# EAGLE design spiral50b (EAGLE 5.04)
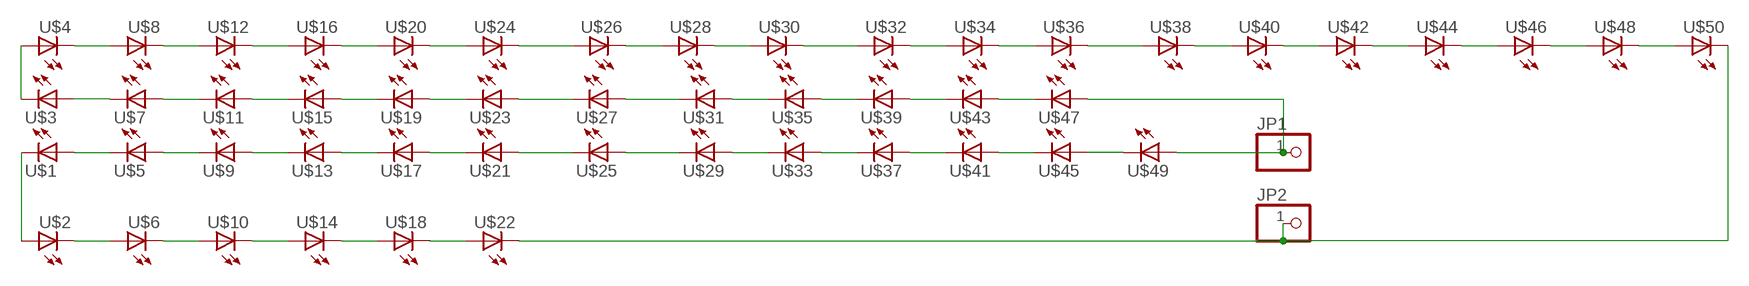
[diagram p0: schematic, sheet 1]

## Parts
JP1  PINHD-1X1  [1X01]
JP2  PINHD-1X1  [1X01]
U$1  LED5MM  [LED5MM]
U$2  LED5MM  [LED5MM]
U$3  LED5MM  [LED5MM]
U$4  LED5MM  [LED5MM]
U$5  LED5MM  [LED5MM]
U$6  LED5MM  [LED5MM]
U$7  LED5MM  [LED5MM]
U$8  LED5MM  [LED5MM]
U$9  LED5MM  [LED5MM]
U$10  LED5MM  [LED5MM]
U$11  LED5MM  [LED5MM]
U$12  LED5MM  [LED5MM]
U$13  LED5MM  [LED5MM]
U$14  LED5MM  [LED5MM]
U$15  LED5MM  [LED5MM]
U$16  LED5MM  [LED5MM]
U$17  LED5MM  [LED5MM]
U$18  LED5MM  [LED5MM]
U$19  LED5MM  [LED5MM]
U$20  LED5MM  [LED5MM]
U$21  LED5MM  [LED5MM]
U$22  LED5MM  [LED5MM]
U$23  LED5MM  [LED5MM]
U$24  LED5MM  [LED5MM]
U$25  LED5MM  [LED5MM]
U$26  LED5MM  [LED5MM]
U$27  LED5MM  [LED5MM]
U$28  LED5MM  [LED5MM]
U$29  LED5MM  [LED5MM]
U$30  LED5MM  [LED5MM]
U$31  LED5MM  [LED5MM]
U$32  LED5MM  [LED5MM]
U$33  LED5MM  [LED5MM]
U$34  LED5MM  [LED5MM]
U$35  LED5MM  [LED5MM]
U$36  LED5MM  [LED5MM]
U$37  LED5MM  [LED5MM]
U$38  LED5MM  [LED5MM]
U$39  LED5MM  [LED5MM]
U$40  LED5MM  [LED5MM]
U$41  LED5MM  [LED5MM]
U$42  LED5MM  [LED5MM]
U$43  LED5MM  [LED5MM]
U$44  LED5MM  [LED5MM]
U$45  LED5MM  [LED5MM]
U$46  LED5MM  [LED5MM]
U$47  LED5MM  [LED5MM]
U$48  LED5MM  [LED5MM]
U$49  LED5MM  [LED5MM]
U$50  LED5MM  [LED5MM]

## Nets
N$1: U$1.A U$5.K(C)
N$2: U$3.A U$7.K(C)
N$3: U$5.A U$9.K(C)
N$4: U$7.A U$11.K(C)
N$5: U$11.A U$15.K(C)
N$6: U$15.A U$19.K(C)
N$7: U$19.A U$23.K(C)
N$8: U$23.A U$27.K(C)
N$9: U$27.A U$31.K(C)
N$10: U$9.A U$13.K(C)
N$11: U$13.A U$17.K(C)
N$12: U$17.A U$21.K(C)
N$13: U$21.A U$25.K(C)
N$14: U$25.A U$29.K(C)
N$15: U$31.A U$35.K(C)
N$16: U$35.A U$39.K(C)
N$17: U$39.A U$43.K(C)
N$18: U$43.A U$47.K(C)
N$19: U$29.A U$33.K(C)
N$20: U$33.A U$37.K(C)
N$21: U$37.A U$41.K(C)
N$22: U$41.A U$45.K(C)
N$23: U$1.K(C) U$2.A
N$24: U$2.K(C) U$6.A
N$25: U$45.A U$49.K(C)
N$26: U$6.K(C) U$10.A
N$27: U$10.K(C) U$14.A
N$28: U$14.K(C) U$18.A
N$29: U$18.K(C) U$22.A
N$30: U$4.K(C) U$8.A
N$31: U$8.K(C) U$12.A
N$32: U$12.K(C) U$16.A
N$33: U$16.K(C) U$20.A
N$34: U$20.K(C) U$24.A
N$35: U$24.K(C) U$26.A
N$36: U$26.K(C) U$28.A
N$37: U$28.K(C) U$30.A
N$38: U$30.K(C) U$32.A
N$39: U$32.K(C) U$34.A
N$40: U$3.K(C) U$4.A
N$41: U$34.K(C) U$36.A
N$42: U$36.K(C) U$38.A
N$43: U$38.K(C) U$40.A
N$44: U$40.K(C) U$42.A
N$45: U$42.K(C) U$44.A
N$46: U$44.K(C) U$46.A
N$47: U$46.K(C) U$48.A
N$48: U$48.K(C) U$50.A
N$49: JP2.1 U$22.K(C) U$50.K(C)
N$51: JP1.1 U$47.A U$49.A

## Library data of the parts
JP1 JP2 = pinhead:PINHD-1X1: PIN HEADER
U$1-U$50 = led(2):LED: LED

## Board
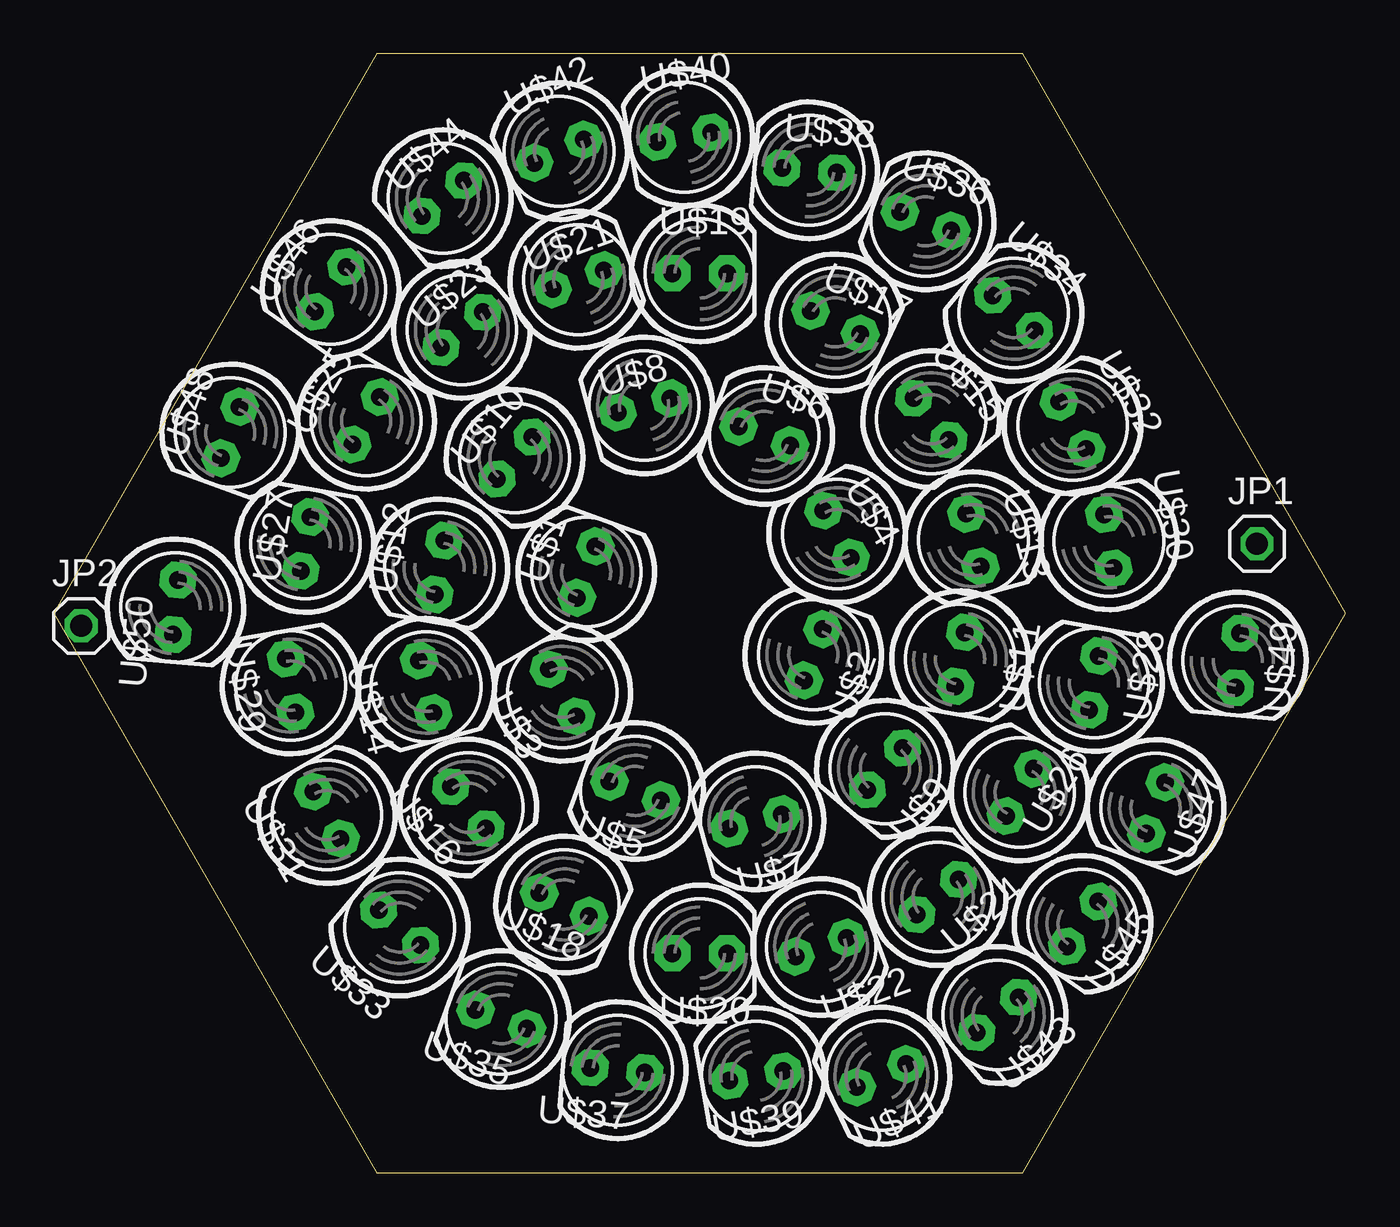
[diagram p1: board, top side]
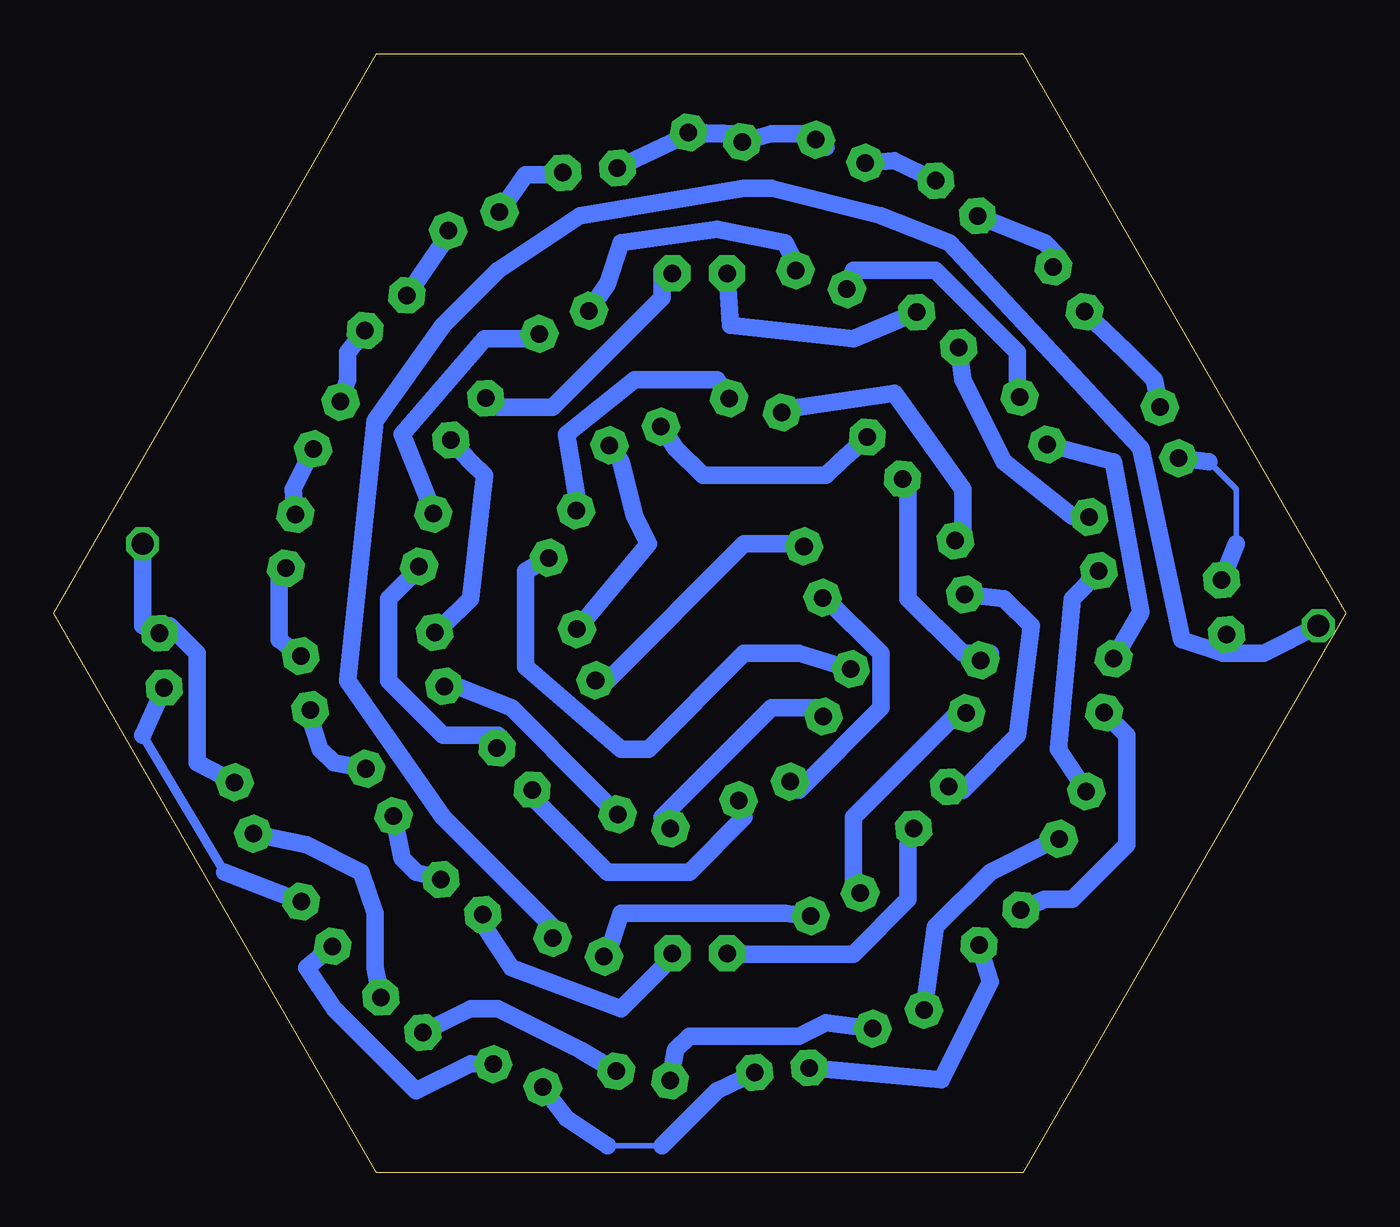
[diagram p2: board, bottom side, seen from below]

Size 60 x 51.96 mm. Coordinates in mm from the lower left corner, seen from the top.
Outline: 15,0 45,0 60,25.98 45,51.96 15,51.96 0,25.98 15,0
Copper layers (1*16): Top 0.035mm / dielectric 1.5mm / Bottom 0.035mm
Design rules "default": minimum track width 10mil, minimum drill 24mil, track to track 8mil, track to pad 8mil, pad to pad 8mil, via to via 8mil, smd to smd 8mil, copper to edge 40mil, drill to drill 8mil, minimum pad ring 10mil, minimum via ring 8mil, stop-mask expansion 4mil, vias tented up to drill 0mil, thermal gap 10mil

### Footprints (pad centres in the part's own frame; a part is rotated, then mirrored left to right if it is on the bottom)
1X01 = drill 1.016 octagon: 1 0,0
LED5MM = drill 0.813 pad 1.676 octagon: A -1.27,0; K 1.27,0

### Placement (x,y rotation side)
JP1  55.88,29.21 0 top
JP2  1.27,25.4 0 top
U$1  24.73,27.9 70 top
U$2  35.27,24.06 70 top
U$3  23.62,22.3 120 top
U$4  36.38,29.66 120 top
U$5  27,17.74 160 top
U$6  33,34.22 160 top
U$7  32.59,16.32 195 top
U$8  27.41,35.64 195 top
U$9  38.6,18.76 230 top
U$10  21.4,33.2 230 top
U$11  42.09,23.85 260 top
U$12  17.91,28.11 260 top
U$13  42.71,29.38 285 top
U$14  17.29,22.58 285 top
U$15  40.75,35 310 top
U$16  19.25,16.96 310 top
U$17  36.3,39.49 335 top
U$18  23.7,12.47 335 top
U$19  30,41.77 0 top
U$20  30,10.19 0 top
U$21  24.36,41.47 20 top
U$22  35.64,10.49 20 top
U$23  18.95,39.15 40 top
U$24  41.05,12.81 40 top
U$25  14.51,34.93 59.9 top
U$26  44.86,17.67 59.9 top
U$27  11.69,29.21 80 top
U$28  48.31,22.75 80 top
U$29  11,22.63 100 top
U$30  49,29.33 100 top
U$31  12.68,16.62 120 top
U$32  47.32,34.71 120 top
U$33  16.06,11.39 140 top
U$34  44.57,39.93 140 top
U$35  20.78,7.14 160 top
U$36  40.49,44.18 160 top
U$37  26.18,4.77 175 top
U$38  35.09,46.55 175 top
U$39  32.63,4.5 190 top
U$40  29.28,48.09 190 top
U$41  38.44,4.52 205 top
U$42  23.46,47.44 205 top
U$43  43.84,7.34 220 top
U$44  18.07,45.26 220 top
U$45  47.78,11.56 235 top
U$46  12.86,41.03 235 top
U$47  51.17,16.95 250 top
U$48  8.19,34.38 250 top
U$49  54.99,23.79 265 top
U$50  5.65,26.26 265 top

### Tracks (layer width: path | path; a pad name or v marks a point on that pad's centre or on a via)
N$1
  Bottom 0.813: U$5.K 25.4,17.78 21.59,21.59 21.59,24.13 24.13,26.67 U$1.A
N$2
  Bottom 0.813: U$3.A 24.13,21.59 26.67,21.59 31.75,16.51 U$7.K
N$3
  Bottom 0.813: U$5.A 27.94,16.51 30.48,13.97 34.29,13.97 38.1,17.78 U$9.K
N$4
  Bottom 0.813: U$7.A 34.92,17.78 38.73,21.59 41.91,22.86 U$11.K
N$5
  Bottom 0.813: U$11.A 41.91,25.4 40.64,26.67 40.01,32.38 40.64,33.02 U$15.K
N$6
  Bottom 0.813: U$19.K 31.75,41.91 31.75,40.64 36.83,35.56 39.37,35.56 U$15.A
N$7
  Bottom 0.813: U$23.K 22.86,38.73 28.57,39.37 U$19.A
N$8
  Bottom 0.813: U$27.K 12.7,30.48 15.88,33.02 17.78,36.83 U$23.A
N$9
  Bottom 0.813: U$31.K 13.34,19.68 12.7,26.67 11.43,27.94 U$27.A
N$10
  Bottom 0.813: U$9.A 39.37,20.32 41.91,20.32 44.45,22.86 44.45,26.67 43.18,27.94 U$13.K
N$11
  Bottom 0.813: U$13.A 42.55,31.11 43.81,34.29 40.01,38.73 38.1,38.73 U$17.K
N$12
  Bottom 0.813: U$21.K 25.4,41.91 26.04,43.18 29.21,43.81 33.66,43.18 34.29,41.27 U$17.A
N$13
  Bottom 0.813: U$25.K 15.24,36.83 15.24,38.1 19.05,41.91 22.86,41.91 U$21.A
N$14
  Bottom 0.813: U$29.K 9.53,26.04 10.79,33.02 U$25.A
N$15
  Bottom 0.813: U$35.K 19.05,11.43 16.51,13.97 13.97,15.24 U$31.A
N$16
  Bottom 0.813: U$39.K 31.11,5.71 30.48,6.35 25.4,6.35 24.13,6.99 U$35.A
N$17
  Bottom 0.813: U$39.A 35.56,5.71 39.37,7.62 40.64,7.62 U$43.K
N$18
  Bottom 0.813: U$43.A 45.09,9.53 45.09,12.06 45.72,13.97 48.26,15.24 U$47.K
N$19
  Bottom 0.813: U$33.K 13.97,12.7 12.7,12.7 10.16,15.24 10.16,20.32 11.43,21.59 U$29.A
N$20
  Bottom 0.813: U$37.K 18.79,4.34 16.51,8.89 U$33.A
N$21
  Bottom 0.254: 31.75,1.27 34.29,1.27
  Bottom 0.813: 31.75,1.27 29.21,3.81 U$37.A | 34.29,1.27 36.2,2.54 U$41.K
N$22
  Bottom 0.813: U$41.A 40.64,5.08 43.18,3.81 46.99,7.62 48.26,9.53 U$45.K
N$23
  Bottom 0.813: U$1.K 25.4,29.21 27.94,29.21 34.29,22.86 U$2.A
N$24
  Bottom 0.813: U$2.K 35.56,25.4 32.38,29.21 33.02,30.48 33.66,33.02 U$6.A
N$25
  Bottom 0.406: 52.07,13.97 55.88,20.32
  Bottom 0.813: U$45.A 52.07,13.97 | 55.88,20.32 U$49.K
N$26
  Bottom 0.813: U$10.A 23.5,33.02 24.13,32.38 29.84,32.38 31.11,33.66 U$6.K
N$27
  Bottom 0.813: U$14.A 16.51,24.13 17.78,24.13 20.32,26.67 20.32,31.75 U$10.K
N$28
  Bottom 0.813: U$14.K 17.78,21.59 22.86,16.51 22.86,12.7 U$18.A
N$29
  Bottom 0.813: U$22.A 34.29,10.16 33.66,12.06 26.04,12.06 U$18.K
N$30
  Bottom 0.813: U$8.A 29.21,36.83 33.02,36.83 36.2,34.29 35.56,30.48 U$4.K
N$31
  Bottom 0.813: U$12.A 17.78,29.21 17.78,31.75 20.95,36.2 25.4,35.56 U$8.K
N$32
  Bottom 0.813: U$12.K 15.88,26.67 14.61,25.4 15.24,20.32 17.78,17.78 U$16.A
N$33
  Bottom 0.813: U$20.A 27.94,10.16 22.86,10.16 20.32,12.7 20.32,15.24 U$16.K
N$34
  Bottom 0.813: U$20.K 31.75,9.53 33.66,7.62 38.73,9.53 40.01,11.43 U$24.A
N$35
  Bottom 0.813: U$24.K 43.18,13.97 43.81,14.61 U$26.A
N$36
  Bottom 0.813: U$26.K 46.99,19.05 47.62,19.68 48.26,21.59 U$28.A
N$37
  Bottom 0.813: U$28.K 49.53,24.77 49.53,27.94 U$30.A
N$38
  Bottom 0.813: U$32.A 48.26,33.02 48.9,31.75 U$30.K
N$39
  Bottom 0.813: U$32.K 46.35,36.83 46.35,38.1 U$34.A
N$40
  Bottom 0.813: U$3.K 25.4,24.13 27.94,24.13 32.38,19.68 33.66,19.68 38.1,23.5 38.1,27.94 U$4.A
N$41
  Bottom 0.813: U$36.A 41.91,43.18 U$34.K
N$42
  Bottom 0.813: U$38.A 36.83,46.35 38.1,46.35 U$36.K
N$43
  Bottom 0.813: U$40.A 27.94,48.26 30.48,48.26 U$38.K
N$44
  Bottom 0.813: U$42.A 24.13,47.62 25.4,48.26 26.67,48.26 U$40.K
N$45
  Bottom 0.813: U$44.A 20.95,46.99 U$42.K
N$46
  Bottom 0.813: U$46.A 13.34,42.55 13.97,43.18 U$44.K
N$47
  Bottom 0.813: U$48.A 8.89,36.83 10.16,38.1 U$46.K
N$48
  Bottom 0.254: 5.08,29.21 5.08,31.75 6.35,33.02
  Bottom 0.813: U$50.A 5.08,29.21 | 6.35,33.02 U$48.K
N$49
  Bottom 0.813: JP2.1 3.81,24.13 5.71,24.13 | 5.71,24.13 7.62,24.77 9.53,33.66 18.41,43.18 21.59,44.45 26.67,45.72 27.94,45.72 35.56,44.45 39.37,41.91 41.91,39.37 45.09,34.92 46.35,22.86 41.91,16.51 36.83,11.43 U$22.K | 5.71,24.13 U$50.K
N$51
  Bottom 0.813: JP1.1 55.88,25.4 U$49.A 54.61,25.4 53.34,24.13 53.34,19.05 U$47.A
